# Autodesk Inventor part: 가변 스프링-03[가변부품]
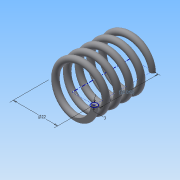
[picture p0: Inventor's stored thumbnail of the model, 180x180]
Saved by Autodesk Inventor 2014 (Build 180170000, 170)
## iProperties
Created: 2015-09
Part Number: 가변 스프링-03[가변부품]
Material: 강철, 탄소
Document SubType Name: Modeling
Designer: study
Density: 7.87 g/cm^3
Appearance: 반연마
Mass: 18.7976 g
Surface Area: 32.4648 cm^2
Volume: 2.38851 cm^3
Author: study
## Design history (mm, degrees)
sketch "스케치1"
  geometry: L1 (0, 0)-(11, 0); L2 (11, 0)-(11, 29.043); L3 (11, 29.043)-(0, 29.043); L4 (0, 29.043)-(0, 0); C1 r 1.5 at (11, 0)
  constraints: 8 end point, 2 parallel, 1 centre point, 1 coincident, 1 horizontal, 1 perpendicular
  dimensions: "d0" = 22 diameter of L2 L4; "d1" = 29.04259 distance of L1.end L2.end (derived); "d2" = 3 diameter of C1
feature "코일1" sketch "스케치1" pitch "d3" = 10; turns "d5" = 5; dims "d4" = 29.04259 (= d1), "d6" = 0, angle "d7" = 90 deg, angle "d8" = 90 deg, "d9" = 0, "d10" = 0
node "작업 평면1"
sketch "스케치2"
  geometry: L1 (-12.5, 0)-(-9.5, 0) reference; L2 (-12.5, 0)-(-9.5, 0) reference; 1 further point
  constraints: 2 horizontal alignment
extrude "돌출1" cut sketch "스케치2" stored distance "d12" = 10; taper "d13" = 0 deg
node "작업 평면2"
sketch "스케치3"
  geometry: L1 (-9.5, 0)-(-12.5, 0) reference; 1 further point
  constraints: 1 horizontal alignment
extrude "돌출2" cut sketch "스케치3" stored distance "d15" = 10; taper "d16" = 0 deg
node "솔리드1"
node "절단 모서리 투영1"
node "절단 모서리 투영2"
node "절단 모서리 투영3"
other parameters: "d11" = 0, "d14" = 29.04259 (= d1)
